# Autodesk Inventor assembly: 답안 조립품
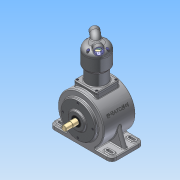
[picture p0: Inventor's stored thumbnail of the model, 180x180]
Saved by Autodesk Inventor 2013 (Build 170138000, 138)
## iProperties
Created: 2015-06
Part Number: 답안 조립품
Document SubType Name: Assembly
Designer: Administrator
Author: Administrator
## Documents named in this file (15)
- C:\Users\Administrator\Desktop\450606V1034\답안 조립품.iam
- C:\Users\Administrator\Desktop\450606V1034\답안 본체.ipt
- C:\Users\Administrator\Desktop\450606V1034\메인 크랭크 축-구동부.ipt
- C:\Users\Administrator\Desktop\450606V1034\메인커버.ipt
- C:\Users\Administrator\Desktop\450606V1034\베어링 6204.ipt
- C:\Users\Administrator\Desktop\450606V1034\베어링 NA 4902.ipt
- C:\Users\Administrator\Desktop\450606V1034\실린더.ipt
- C:\Users\Administrator\Desktop\450606V1034\실린더헤드.ipt
- C:\Users\Administrator\Desktop\450606V1034\오일실.ipt
- C:\Users\Administrator\Desktop\450606V1034\커넥팅 로드.ipt
- C:\Users\Administrator\Desktop\450606V1034\크랭크 서브축.ipt
- C:\Users\Administrator\Desktop\450606V1034\피스톤 핀.ipt
- C:\Users\Administrator\Desktop\450606V1034\피스톤.ipt
- C:\Users\Administrator\Desktop\450606V1034\M5x0.8.ipt
- C:\Users\Administrator\Desktop\450606V1034\M4x0.7.ipt
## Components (14 placed, 4 different names)
1. 피스톤 핀:1 — 플러쉬:1
2. 피스톤:1 — 플러쉬:1
3. M5x0.8:1
4. M5x0.8:2
5. M5x0.8:3
6. M5x0.8:4
7. M4x0.7:3
8. M4x0.7:6
9. M4x0.7:7
10. M4x0.7:8
11. M4x0.7:4
12. M4x0.7:9
13. M4x0.7:10
14. M4x0.7:11
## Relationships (1: Flush 1)
- 플러쉬:1 [Flush]: 피스톤 핀:1 ↔ 피스톤:1
